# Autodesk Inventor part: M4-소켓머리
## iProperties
IsCustomPart: 0
Company: 한국ATC센터
Created: 2014-08
Part Number: M4-소켓머리
Material: 강, 연강
Description: 6각머리 태핑 나사
Document SubType Name: Modeling
Standard: KS B 1003
Designer: KYOUNG IL JANG
Standards Organization: KS
Language: ko-KR
Size Designation: M 4 x 12
Categories: <MemberInstance><Categories><Category DisplayName="조임쇠" InternalName="e4da775c-781d-43d5-af7c-5136215cf5a6" Mnemonic="FSTN"><Category DisplayName="볼트" InternalN
Density: 1 g/cm^3
Checked By: KYOUNG IL JANG
Author: KYOUNG IL JANG
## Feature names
1. Fillet2
